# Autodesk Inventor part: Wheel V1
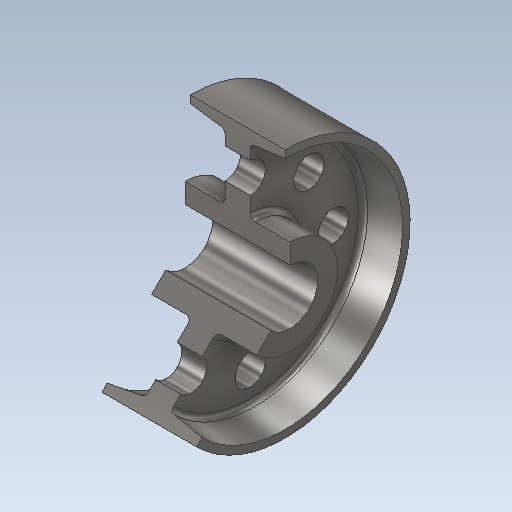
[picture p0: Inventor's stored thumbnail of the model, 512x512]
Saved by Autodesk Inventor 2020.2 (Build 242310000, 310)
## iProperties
Created: 2018-06
Part Number: Wheel V1
Material: Stainless Steel
Document SubType Name: Modeling
Designer: Power User
Density: 8 g/cm^3
Appearance: Semi-Polished
Mass: 618.44 g
Surface Area: 270.831 cm^2
Volume: 77.305 cm^3
Author: Power User
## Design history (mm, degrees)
sketch "Sketch1"
  geometry: L1 (-34.726, 0)-(34.726, 0); L2 (0, 36.063)-(0, -36.063); L3 (0, 11)-(-21, 11); L4 (-21, 19)-(-5, 19); L5 (-5, 19)-(-5, 45.032); L6 (-5, 45.032)-(-19, 47); L7 (-19, 47)-(-19, 50); L8 (-19, 50)-(0, 50); L9 (-21, 19)-(-21, 11); L10 (0, 11)-(21, 11); L11 (21, 19)-(5, 19); L12 (5, 19)-(5, 45.032); L13 (5, 45.032)-(19, 47); L14 (19, 47)-(19, 50); L15 (19, 50)-(0, 50); L16 (21, 19)-(21, 11); 2 further points
  constraints: 32 end point, 6 symmetric about line, 3 perpendicular, 2 horizontal, 2 midpoint, 2 point on line, 2 vertical, 1 coincident, 1 other
  dimensions: "d4" = 19 distance of L7.end L8.end; "d5" = 10 diameter of L5 L2; "d6" = 8 deg angle of L4 L6; "d7" = 42 diameter of L9 L2; "d24" = 11 distance from line of L3 point (0, 0); "d25" = 19 distance from line of L4 point (0, 0); "d26" = 47 vertical distance of L6.end point (0, 0); "d27" = 50 distance from line of point (0, 0) L8
revolve "Revolution1" sketch "Sketch1" stored, may be unused: angle "d8" = 225 deg; dims "d9" = 45 deg
sketch "Sketch2" dims "d12" = 33.2
  geometry: C1 r 6.1 at (0, 14.2); C2 r 6.1 at (-23.476, 4.476); C3 r 6.1 at (-33.2, -19); C4 r 6.1 at (-23.476, -42.476); C5 r 6.1 at (0, -52.2); C6 r 6.1 at (23.476, -42.476); C7 r 6.1 at (33.2, -19); C8 r 6.1 at (23.476, 4.476); 2 further points
  constraints: 8 centre point, 2 vertical alignment, 1 coincident, 19 other
  dimensions: "d10" = 12.2 diameter of C1; "d15" = 360 deg dimension on point (0, -19) C1.centre (derived)
hole "Hole1" sketch "Sketch2" at (23.476, 4.476), (33.2, -19), (23.476, -42.476), (0, -52.2), (-23.476, -42.476), (0, 14.2) diameter "d17" = 12.2; stored, may be unused: countersink angle "d21" = 90 deg, drill point angle "d23" = 118 deg; dims "d18" = 6, "d19" = 20, "d20" = 2, "d22" = 8
fillet "Fillet1" dims "d28" = 2
workplane "Work Plane1"
body "Solid1"
